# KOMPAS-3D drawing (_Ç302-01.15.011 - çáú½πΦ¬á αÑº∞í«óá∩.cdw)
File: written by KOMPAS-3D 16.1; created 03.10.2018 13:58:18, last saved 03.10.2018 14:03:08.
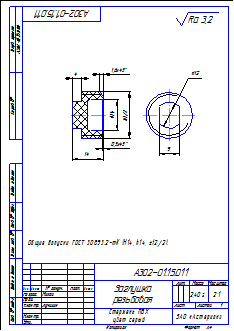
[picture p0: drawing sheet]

Sheet 1: A4, portrait

Title block, sheet 1: name: Заглушка / резьбовая; designation: А302-01.15.011; mass: 2,40 г; scale: 2:1; sheets: 1; organisation: ЗАО «Астерион»; sheet format: A4; stored path: \\192.168.87.28\Konstructor_doc\Мембранные насосы\Мембранный электропривод\А302-00.00.000 - ASTRA-302 (МЭ200)\3Д ПВХ\А302-01.15.011 - Заглушка резьбовая.cdw; drawn by: Милов; technical control: Лучихин

Views: Вид 1, Местный разрез 1, Спереди, Проекционный вид 2
Referenced files in Z:\Мембранные насосы\Мембранный электропривод\А302-00.00.000 - ASTRA-302 (МЭ200)\3Д ПВХ\: А302-01.15.011 - Заглушка резьбовая.m3d
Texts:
  Стержень ПВХ
  цвет серый
  Общие допуски ГОСТ 30893.2-mK (H14, h14,  t2/2).
  Ra 3,2
Dimensions and other numbers on the sheet: 14; 1,6; 4; 0,5; 9; 12; 2:1; 1; 2,40 г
